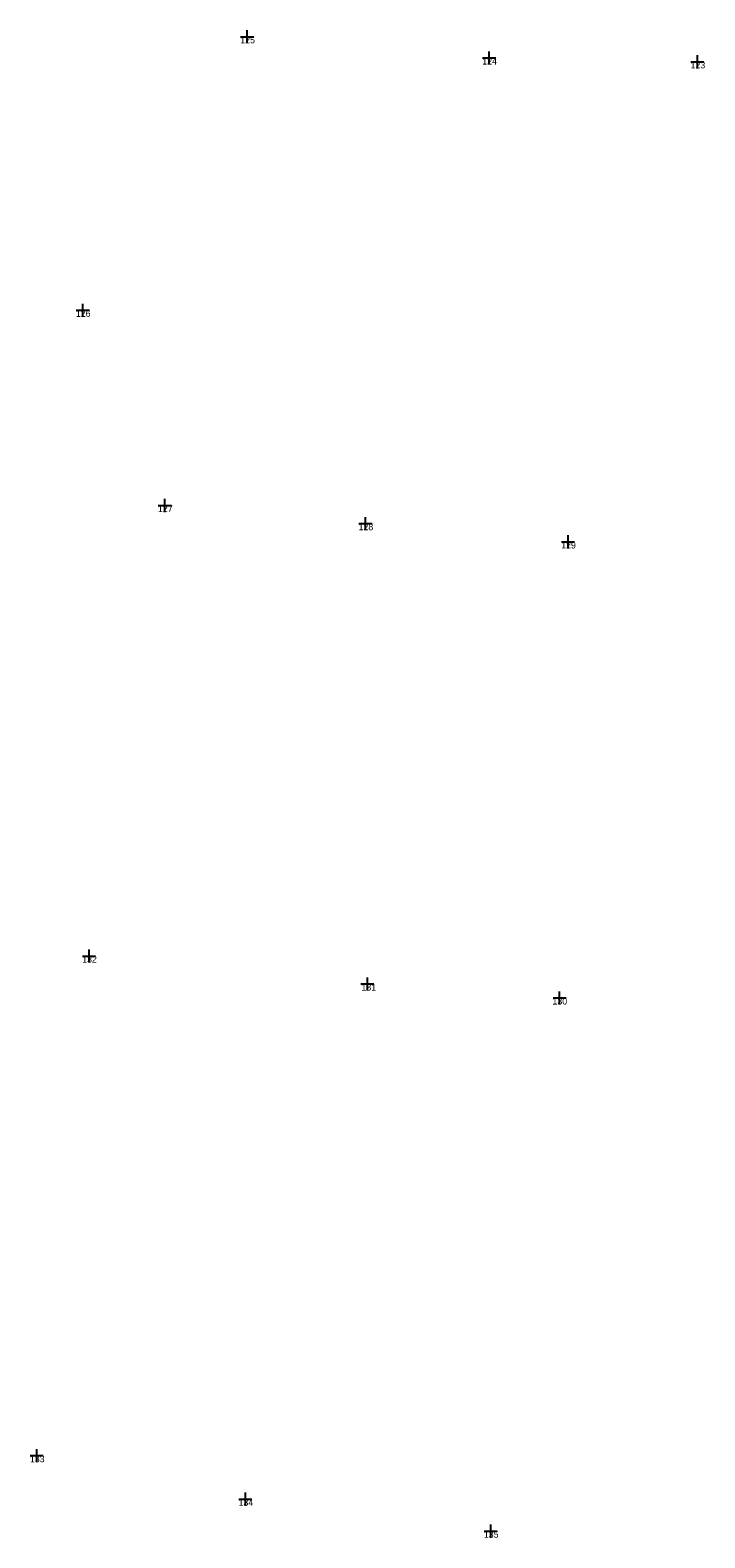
# Model space of a CAD drawing. Extents: x -706655 to -706193, y -1036183 to -1034979.
# Drawn here: x -706248.5 to -706197.3, y -1035711.9 to -1035597.5 of the extents above; entities that cross this region are included whole.
import ezdxf

# ---------------------------------------------------------------- set-up
doc = ezdxf.new("R2010")
doc.units = 0
doc.layers.add('čísla bodu', color=7, linetype='Continuous')

msp = doc.modelspace()

# ---------------------------------------------------------------- linework, layer by layer
at = {"layer": 'čísla bodu'}
for p, q in [((-706232.52, -1035597.98), (-706231.52, -1035597.98)), ((-706232.02, -1035598.48), (-706232.02, -1035597.48)), ((-706232.02, -1035597.98), (-706232.02, -1035597.98)), ((-706213.65, -1035600.09), (-706213.65, -1035599.09)), ((-706197.84, -1035600.38), (-706197.84, -1035599.38)), ((-706214.15, -1035599.59), (-706213.15, -1035599.59)), ((-706213.65, -1035599.59), (-706213.65, -1035599.59)), ((-706198.34, -1035599.88), (-706197.34, -1035599.88)), ((-706197.84, -1035599.88), (-706197.84, -1035599.88)), ((-706244.99, -1035618.74), (-706243.99, -1035618.74)), ((-706244.49, -1035619.24), (-706244.49, -1035618.24)), ((-706244.49, -1035618.74), (-706244.49, -1035618.74)), ((-706238.77, -1035633.55), (-706237.77, -1035633.55)), ((-706238.27, -1035634.05), (-706238.27, -1035633.05)), ((-706238.27, -1035633.55), (-706238.27, -1035633.55)), ((-706223.54, -1035634.93), (-706222.54, -1035634.93)), ((-706223.04, -1035635.43), (-706223.04, -1035634.43)), ((-706223.04, -1035634.93), (-706223.04, -1035634.93)), ((-706207.66, -1035636.82), (-706207.66, -1035635.82)), ((-706208.16, -1035636.32), (-706207.16, -1035636.32)), ((-706207.66, -1035636.32), (-706207.66, -1035636.32)), ((-706244.52, -1035667.75), (-706243.52, -1035667.75)), ((-706244.02, -1035668.25), (-706244.02, -1035667.25)), ((-706244.02, -1035667.75), (-706244.02, -1035667.75)), ((-706223.39, -1035669.87), (-706222.39, -1035669.87)), ((-706222.89, -1035670.37), (-706222.89, -1035669.37)), ((-706222.89, -1035669.87), (-706222.89, -1035669.87)), ((-706208.3, -1035671.43), (-706208.3, -1035670.43)), ((-706208.8, -1035670.93), (-706207.8, -1035670.93)), ((-706208.3, -1035670.93), (-706208.3, -1035670.93)), ((-706248.49, -1035705.67), (-706247.49, -1035705.67)), ((-706247.99, -1035706.17), (-706247.99, -1035705.17)), ((-706247.99, -1035705.67), (-706247.99, -1035705.67)), ((-706232.65, -1035708.97), (-706231.65, -1035708.97)), ((-706232.15, -1035709.47), (-706232.15, -1035708.47)), ((-706232.15, -1035708.97), (-706232.15, -1035708.97)), ((-706214.03, -1035711.4), (-706213.03, -1035711.4)), ((-706213.53, -1035711.9), (-706213.53, -1035710.9)), ((-706213.53, -1035711.4), (-706213.53, -1035711.4))]:
    msp.add_line(p, q, dxfattribs=at)

# ---------------------------------------------------------------- texts
for s, p in [('125', (-706232.54, -1035598.48)), ('124', (-706214.17, -1035600.09)), ('123', (-706198.36, -1035600.38)), ('126', (-706245.02, -1035619.24)), ('127', (-706238.79, -1035634.05)), ('128', (-706223.56, -1035635.43)), ('129', (-706208.18, -1035636.82)), ('132', (-706244.54, -1035668.25)), ('131', (-706223.34, -1035670.37)), ('130', (-706208.84, -1035671.43)), ('133', (-706248.51, -1035706.17)), ('134', (-706232.67, -1035709.47)), ('135', (-706214.05, -1035711.9))]:
    msp.add_text(s, height=0.5, dxfattribs=at).set_placement(p)

doc.saveas('drawing.dxf')
